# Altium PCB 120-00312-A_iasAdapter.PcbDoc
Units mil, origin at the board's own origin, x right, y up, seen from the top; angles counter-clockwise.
Board outline 1760 x 899 mil, 4 copper layers (Top Layer, L2(GND), L3(V_2V8), Bottom Layer), stack 40.578 mil thick; 12 components, 22 nets, 104 pads, 83 vias.
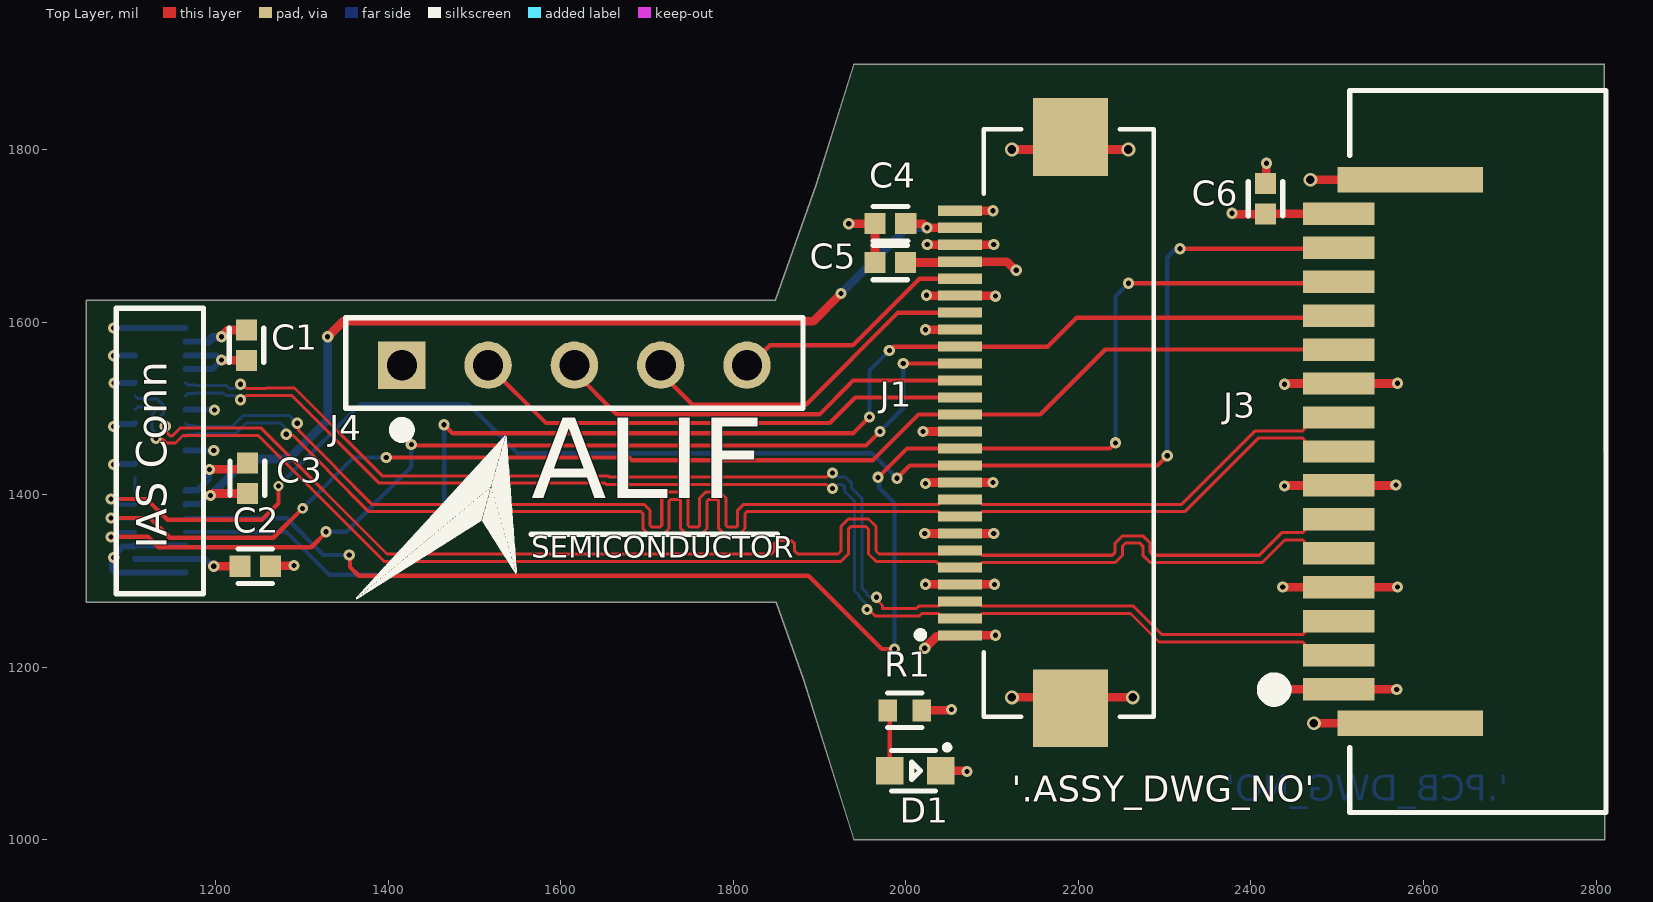
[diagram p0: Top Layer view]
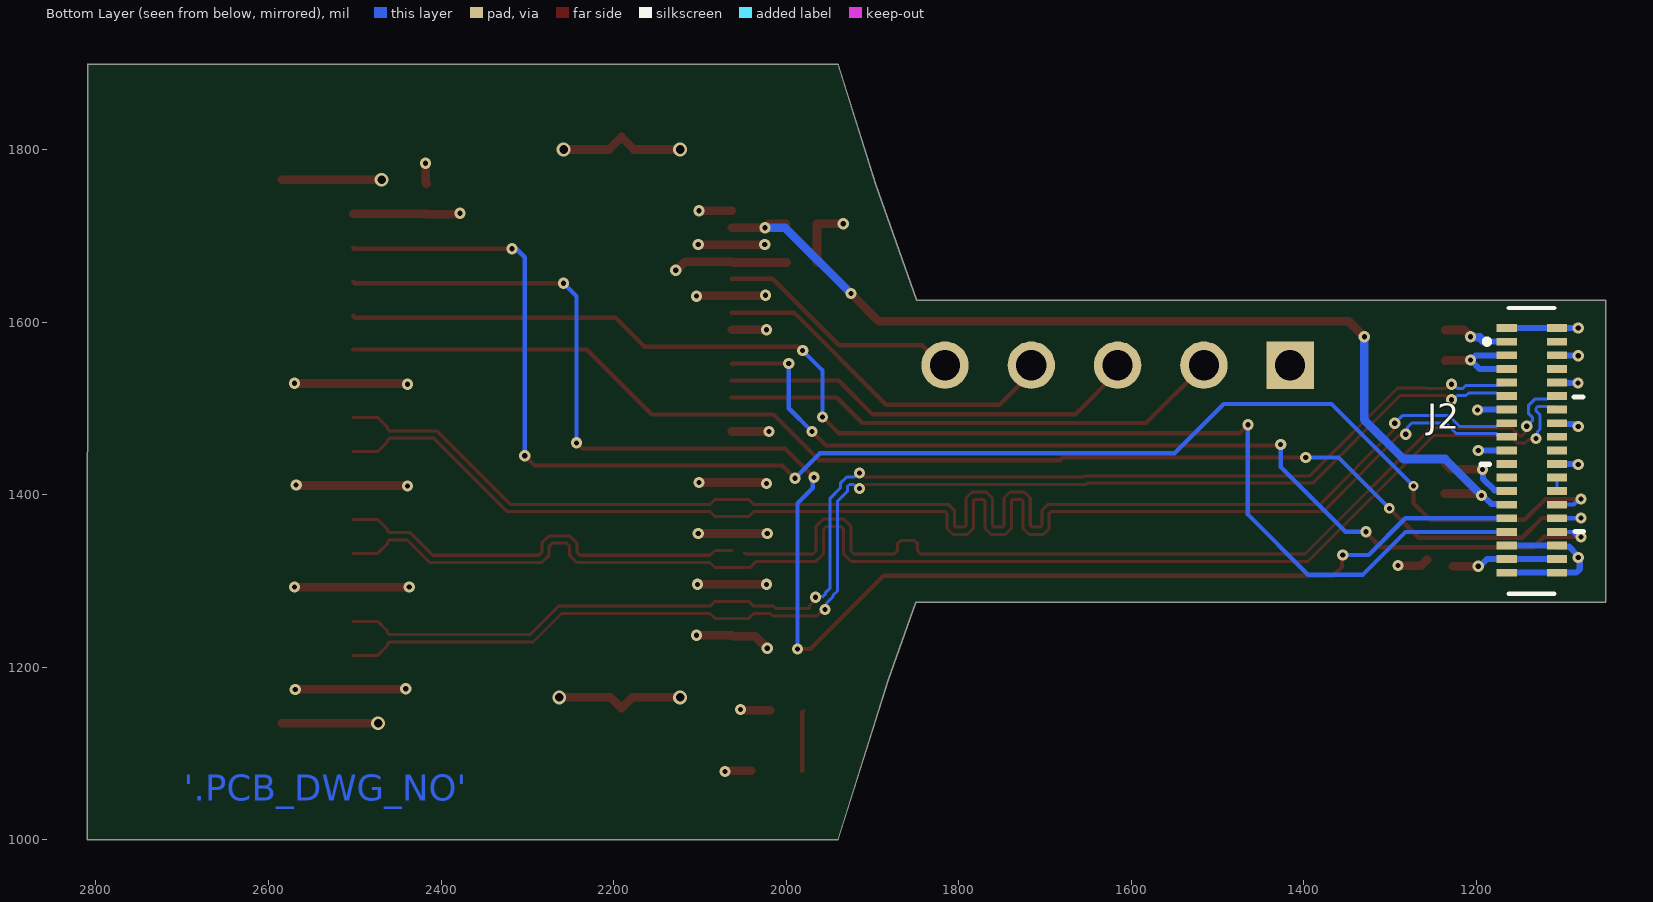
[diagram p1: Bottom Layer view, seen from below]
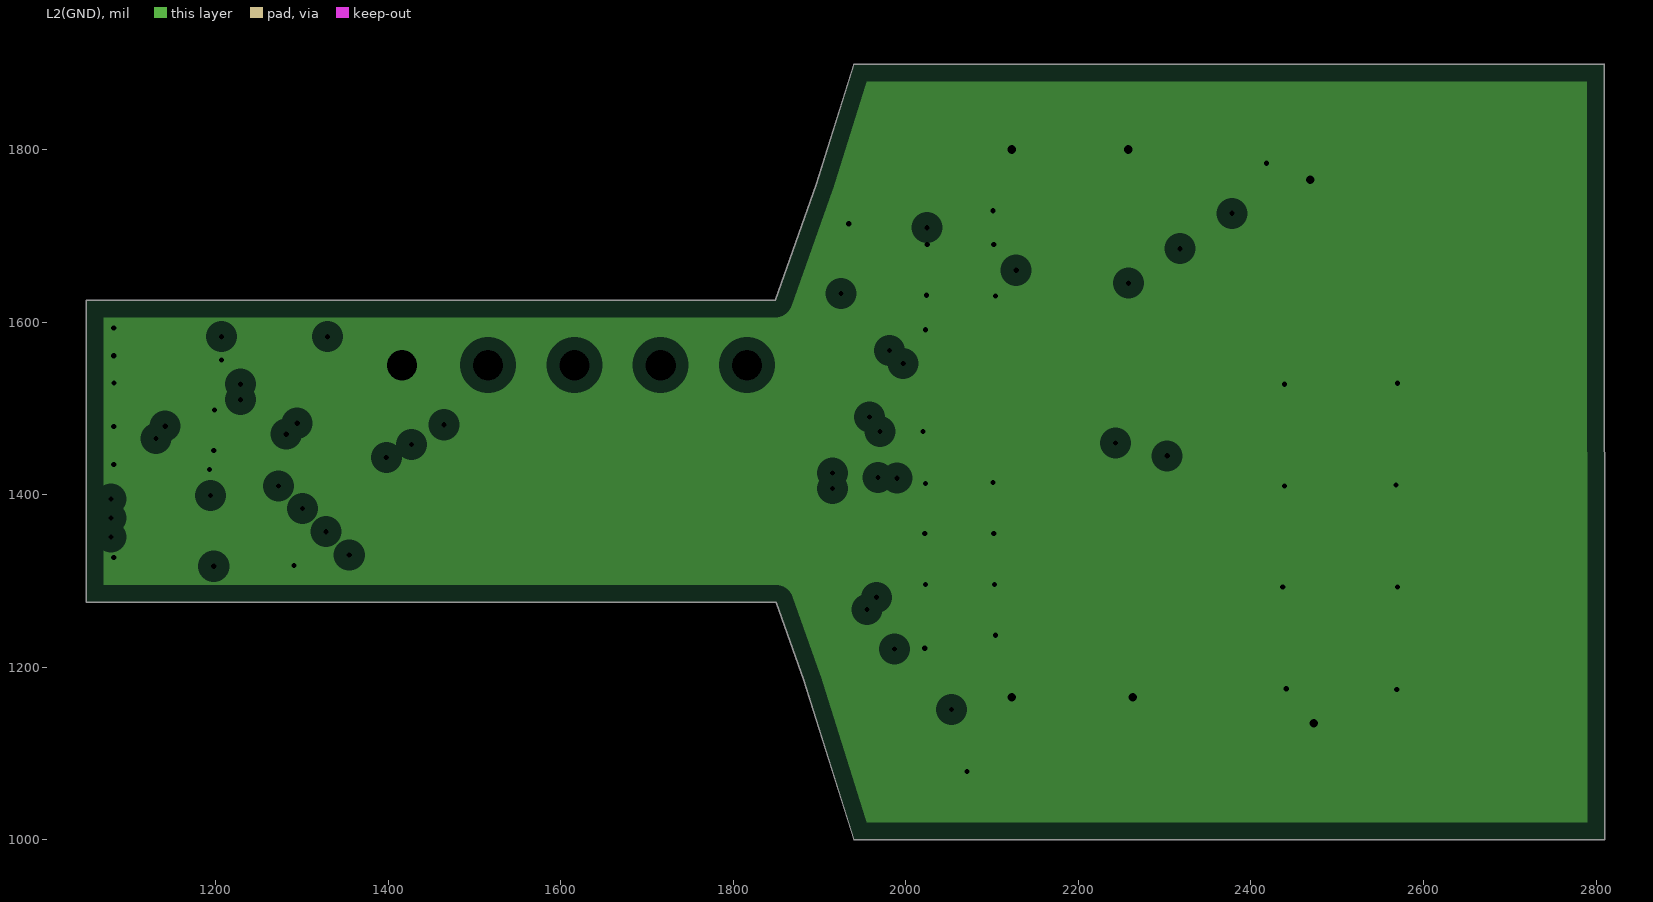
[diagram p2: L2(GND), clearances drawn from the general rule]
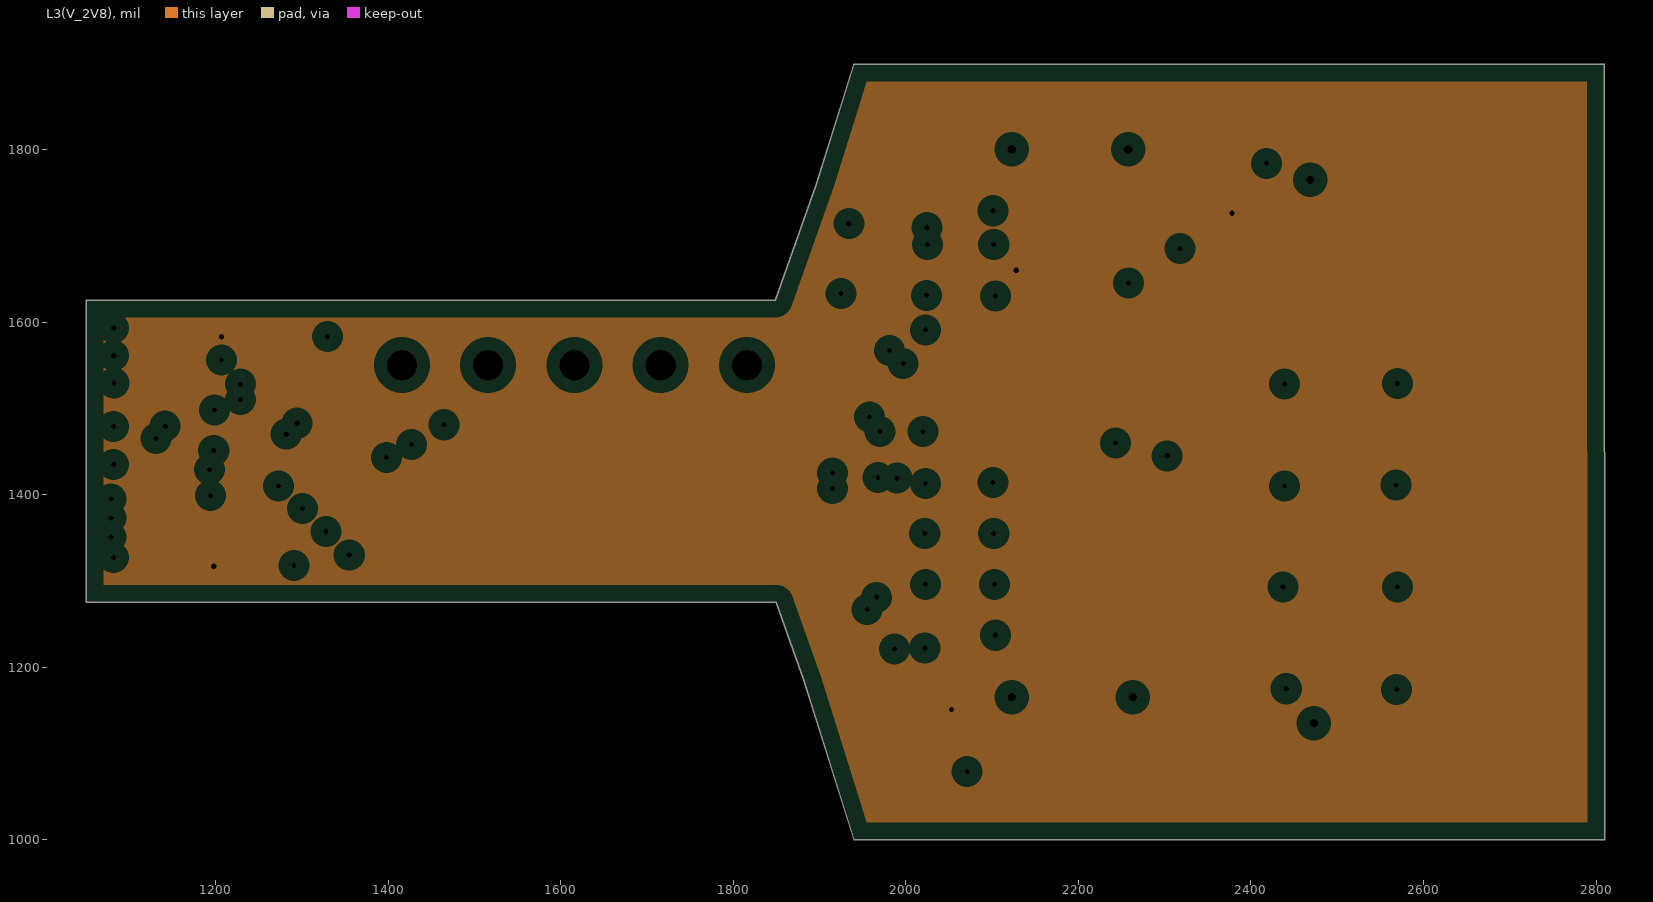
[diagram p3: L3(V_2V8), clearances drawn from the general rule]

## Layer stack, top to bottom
Top Solder: solder mask 0.4, Solder Resist, Dk 3.5
Top Layer: signal copper 1.4
Dielectric 2: prepreg 4.2, PP-006, Dk 4.1
L2(GND): plane copper 0.689, net GND
Dielectric 1: dielectric 28, FR-4, Dk 4.7
L3(V_2V8): plane copper 0.689, net V_2V8
Dielectric 3: prepreg 4.2, PP-006, Dk 4.1
Bottom Layer: signal copper 1.4
Bottom Solder: solder mask 0.4, Solder Resist, Dk 3.5

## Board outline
1940,1000 1882,1185 1850,1275 1050,1275 1050,1625 1849,1625 1896.5,1759.5 1940,1899 2809.4,1899 2809.55,1898.85 2810,1000

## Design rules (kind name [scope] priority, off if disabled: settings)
BoardOutlineClearance [All] p1: gap=10 ignorepadtopadclearanceinfootprint=FALSE except(0: Arc-SplitContinuation Track-SplitContinuation SMDPad-SplitContinuation THPad-SplitContinuation Via-SplitContinuation Fill-SplitContinuation Poly-SplitContinuation Region-SplitContinuation Text-SplitContinuation; 5: Fill-OutlineEdge Poly-OutlineEdge Region-OutlineEdge Text-OutlineEdge; 15: Arc-OutlineEdge Track-OutlineEdge SMDPad-OutlineEdge THPad-OutlineEdge Via-OutlineEdge)
Clearance [All] p1: gap=5 ignorepadtopadclearanceinfootprint=FALSE
DiffPairsRouting [InDifferentialPairClass('All Differential Pairs')] p1: maxlimit=5 minlimit=3 mostfreqgap=5 toplayer_minwidth=3.5 toplayer_maxwidth=4.6 toplayer_prefwidth=4.6 bottomlayer_minwidth=3.5 bottomlayer_maxwidth=4.6 bottomlayer_prefwidth=4.6 maxuncoupledlength=100
MatchedLengths MatchLengths_xSignals_J2_J1 [InxSignalClass('xSignals_J2_J1_MatchLengthsClass')] p1: tolerance=20 checknetsindiffpair=FALSE checkdiffpairvsdiffpair=TRUE checkxsignals=TRUE checkothers=TRUE
MinimumSolderMaskSliver [All] p1: minsoldermaskwidth=0
PlaneClearance [All] p1: clearance=15
PlaneConnect GroundPlane [All] p1: planeconnectstyle=Direct reliefexpansion=20 reliefentries=4 reliefconductorwidth=10 reliefairgap=10
PolygonConnect [InNet('GND')] p1: connectstyle=Direct reliefconductorwidth=10 reliefentries=4 polygonreliefangle="90 Angle" airgapwidth=10
RoutingVias [All] p1: holewidth=28 width=50 viastyle="Through Hole" minholewidth=6 minwidth=12 maxholewidth=10 maxwidth=16
SilkToSilkClearance [All] p1: silktosilkclearance=4
SilkToSolderMaskClearance [IsPad] p1: minsilkscreentomaskgap=4 clearancetoexposedcopper=TRUE
SolderMaskExpansion [All] p1: expansion=4 istentingtop=FALSE
Width [All] p1: maxlimit=10 minlimit=3 preferedwidth=5 minimp=50.000000 maximp=50.000000 favimp=50.000000
24 further rules are at their usual default settings.

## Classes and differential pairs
differential pair class MIPI_CSI_C: MIPI_CSI_C
differential pair class MIPI_CSI_1: MIPI_CSI_1
differential pair class MIPI_CSI_0: MIPI_CSI_0
component class 1-RevisionHistory: ZF1 ZLBL1
differential pair MIPI_CSI_C: +MIPI_CSI_C_P -MIPI_CSI_C_N
differential pair MIPI_CSI_1: +MIPI_CSI_1_P -MIPI_CSI_1_N
differential pair MIPI_CSI_0: +MIPI_CSI_0_P -MIPI_CSI_0_N

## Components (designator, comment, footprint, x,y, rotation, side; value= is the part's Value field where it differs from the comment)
C1 "Cap" CAPC0402-01 1236,1573 r90 top value=100n
C2 "Cap" CAPC0402-01 1246,1317 r180 top value=100n
C3 "Cap" CAPC0402-01 1237,1419 r270 top value=100n
C4 "Cap" CAPC0402-01 1982.28,1714 r0 top value=100n
C5 "Cap" CAPC0402-01 1982,1669 r0 top value=100n
C6 "Cap" CAPC0402-01 2417,1742.72 r270 top value=100n
D1 "D LED2" LED_0603-GRN_AK 2011,1080 r0 top value=GREEN
J1 "5051102696" CONN_FPC_BOT-ENT_FRONT-LOCK_0.50_26 2183,1483.43 r90 top locked
J2 "BM20B(0.8)-34DP-0.4V(51)" CONN_FPC_BM20B(0.8)-34DP-0.4V(51) 1135.87,1451.25 r270 bottom locked
J3 "SFW15R-2STE1LF" CONN_FPC_BOT-ENT_FRONT-LOCK_1.0_15 2663,1450 r90 top locked
J4 "TSW-105-07-G-S" CONN_SAMTEC_CON5_1X5_TU_TSW_dni 1616,1550 r0 top
R1 "Res3" RESC0402-01 1999,1150 r180 top value=1K82

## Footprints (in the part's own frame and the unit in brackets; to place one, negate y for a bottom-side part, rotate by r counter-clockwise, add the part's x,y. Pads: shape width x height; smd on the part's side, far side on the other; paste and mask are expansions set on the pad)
CAPC0402-01 [mm] "Chip Capacitor, Body 1.0x0.5mm, Height 0.6mm, IPC Medium Density"
  rect 0.62x0.62 smd: 1(-0.45,0) 2(0.45,0)
  silkscreen extent -0.51,-0.51 0.51,0.51, body extent -0.55,-0.3 0.55,0.3, height 0.6
CONN_FPC_BM20B(0.8)-34DP-0.4V(51) [mm]
  rect 0.23x0.6 smd paste-1 mask+0.05: 1(-3.2,-0.74) 2(-2.8,-0.74) 3(-2.4,-0.74) 4(-2,-0.74) 5(-1.6,-0.74) 6(-1.2,-0.74) 7(-0.8,-0.74) 8(-0.4,-0.74) 9(0,-0.74) 10(0.4,-0.74) 11(0.8,-0.74) 12(1.2,-0.74) 13(1.6,-0.74) 14(2,-0.74) 15(2.4,-0.74) 16(2.8,-0.74) 17(3.2,-0.74) 18(3.2,0.74) 19(2.8,0.74) 20(2.4,0.74) 21(2,0.74) 22(1.6,0.74) 23(1.2,0.74) 24(0.8,0.74) 25(0.4,0.74) 26(0,0.74) 27(-0.4,0.74) 28(-0.8,0.74) 29(-1.2,0.74) 30(-1.6,0.74) 31(-2,0.74) 32(-2.4,0.74) 33(-2.8,0.74) 34(-3.2,0.74) 35(3.6,-0.74) 36(3.6,0.74) 37(-3.6,-0.74) 38(-3.6,0.74)
  silkscreen extent -4.19,-1.5 4.22,1.52, body extent -4.1,-0.92 4.1,0.86, height 0.66
CONN_FPC_BOT-ENT_FRONT-LOCK_0.50_26 [mm]
  rect 0.3x1.3 smd: 1(-6.262,3.048) 2(-5.762,3.048) 3(-5.262,3.048) 4(-4.762,3.048) 5(-4.262,3.048) 6(-3.762,3.048) 7(-3.262,3.048) 8(-2.762,3.048) 9(-2.262,3.048) 10(-1.762,3.048) 11(-1.262,3.048) 12(-0.762,3.048) 13(-0.262,3.048) 14(0.238,3.048) 15(0.738,3.048) 16(1.238,3.048) 17(1.738,3.048) 18(2.238,3.048) 19(2.738,3.048) 20(3.238,3.048) 21(3.738,3.048) 22(4.238,3.048) 23(4.738,3.048) 24(5.238,3.048) 25(5.738,3.048) 26(6.238,3.048)
  rect 2.286x2.2 smd: MT1(-8.407,-0.202) MT2(8.407,-0.202)
  silkscreen extent -8.66,-2.65 8.64,4.32, body extent -8.68,-2.68 8.62,3.07, height 2
CONN_FPC_BOT-ENT_FRONT-LOCK_1.0_15 [mil] "Raspberry PI 15 pin camera connector"
  rect 26x83 smd paste+0 mask+0: 1(-275.59,161.06) 2(-236.22,161.06) 3(-196.85,161.06) 4(-157.48,161.06) 5(-118.11,161.06) 6(-78.74,161.06) 7(-39.37,161.06) 8(0,161.06) 9(39.37,161.06) 10(78.74,161.06) 11(118.11,161.06) 12(157.48,161.06) 13(196.85,161.06) 14(236.22,161.06) 15(275.59,161.06)
  rect 30x169 smd paste+0 mask+0: MT1(-314.96,78.38) MT2(314.96,78.38)
  silkscreen extent -418,-149 418,246, body extent -409,-66 409,190, height 106
CONN_SAMTEC_CON5_1X5_TU_TSW_dni [mil]
  rect 55x55 / inner round 60 / far side rect 55x55 hole 35 paste-99999 mask+0: 1(-200,0)
  round 55 / inner round 60 / far side round 55 hole 35 paste-99999 mask+0: 2(-100,0) 3(0,0) 4(100,0) 5(200,0)
  silkscreen extent -265,-80 265,55
LED_0603-GRN_AK [mm] "SMT LED 0603 Green"
  rect 0.8x0.8 smd: A(-0.75,0) K(0.75,0)
  silkscreen extent -0.7,-0.6 0.97,0.71, body extent -0.8,-0.4 0.8,0.4, height 0.8
RESC0402-01 [mm] "Chip Resistor, Body 1.0x0.5mm, IPC Medium Density"
  rect 0.55x0.65 smd: 1(-0.5,0) 2(0.5,0)
  silkscreen extent -0.51,-0.51 0.51,0.51, body extent -0.52,-0.27 0.53,0.28, height 0.4

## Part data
C1 C2 C3 C4 C5 C6: library part Cap_SMT, "Cap,100nF,10%,50V,X7R,0402", Manufacturer 1=TDK, Manufacturer 2=Samsung, Manufacturer 3=Walsin, Manufacturer Part Number 1=C1005X7R1H104K050BE, Manufacturer Part Number 2=CL05B104KB54PNC, Manufacturer Part Number 3=0402B104K500CT, Tolerance=10%, Voltage=50V
D1: "Diode,LED,Green 573nm,300mcd @ 20mA,0603", Manufacturer 1=Wurth, Manufacturer Part Number 1=150060VS86000
J1: library part Conn_FFC_BOT_FRONT-LOCK_0.50_26pin, "Conn,FlatFlex,26 pin,0.50mm,bottom-entry,front-lock,SMT", Manufacturer 1=Molex, Manufacturer 2=HiRose, Manufacturer Part Number 2=TF31-26S-0.5SH(800)
J2: library part CONN_HIROSE_BM20_FPC_34PIN_0.4MM_CAM_MODULE, "Conn,FPC,34 pin,0.4mm pitch, 0,8mm height,SMT", Manufacturer 1=HiRose
J3: library part Conn_FFC_BOT_SLIDE-LOCK_1.00_15pin, "Conn,FlatFlex,15 pin,1.00mm,bottom-entry,slide-locking,SMT", Manufacturer 1=Amphenol
J4: library part Hdr_M_1X5_2M54_STRT_UNSHROUD, "DNI,Hdr, 0.025\" SQ Post Header, Through-hole, Vertical, 2.54 mm Pitch, 5-Pin, Male", Manufacturer=Samtec, Temperature Range="-55 to 125 degC"
R1: "Res,1K82,1%,100ppm,0402", Manufacturer 1=Stackpol, Manufacturer 2=Yageo, Manufacturer 3=Bourns, Manufacturer Part Number 1=RMCF0402FT1K82, Manufacturer Part Number 2=RC0402FR-071K82L, Manufacturer Part Number 3=CR0402-FX-1821GLF, Tolerance=1%

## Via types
v1: diameter 13, hole 6, Top Layer to Bottom Layer, 75 vias
v2: diameter 16, hole 10, Top Layer to Bottom Layer, 6 vias
v3: diameter 12, hole 6, Top Layer to Bottom Layer, 2 vias

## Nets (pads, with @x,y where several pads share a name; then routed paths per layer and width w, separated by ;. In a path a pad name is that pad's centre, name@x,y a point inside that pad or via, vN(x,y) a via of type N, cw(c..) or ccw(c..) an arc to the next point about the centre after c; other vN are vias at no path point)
CXT_SEL: J1.22 J4.5 | length 288.5
  Top Layer w5: J4.5 1819.5,1550 1842.5,1573 1938.73,1573 2016.01,1650.28 J1.22
FLASH: J1.18 J2.15 J3.12 | length 1582.9
  Top Layer w5: v1(1465,1481) 1475,1471 1939,1471 v1(1958,1490) ; v1(1981,1567) 1985.54,1571.54 J1.18 2164.54,1571.54 2198,1605 2499.46,1605 J3.12
  Bottom Layer w5: J2.15 1282.24,1356.76 1332,1307 1395,1307 1465,1377 v1(1465,1481) ; v1(1958,1490) 1958,1544 v1(1981,1567)
GND: C1.1 C2.1 C3.1 C4.1 C5.1 C6.1 D1.K J1.1 J1.4 J1.7 J1.10 J1.13 J1.19 J1.21 J1.24 J1.26 J1.MT1 J1.MT2 J2.2 J2.3 J2.6 J2.9 J2.12 J2.16 J2.19 J2.25 J2.28 J2.31 J2.33 J2.35 J2.36 J2.37 J2.38 J3.1 J3.4 J3.7 J3.10 J3.MT1 J3.MT2 J4.1 | length 2476.2
  Top Layer w10: v1(1193,1429) 1193.57,1429.57 1229.86,1429.57 C3.1 ; v1(1207,1556) 1207.36,1555.64 1235.64,1555.64 C1.1 ; C2.1@1257.32,1324.57 1264.4,1317.5 1290.5,1317.5 v1(1291,1318) ; v1(1934,1714) C4.1 1964.43,1713.86 1964.43,1669.14 C5.1 ; v1@2019,1473 2019.11,1473.11 J1.13 ; v1(2022,1355) J1.7 v1(2102,1355) ; v1@2022.57,1222.57 2035.98,1235.98 2062.09,1235.98 J1.1 2103.89,1236.89 v1(2104,1237) ; v1(2023,1413) 2024,1413 2025.06,1414.06 J1.10 2100.94,1414.06 v1(2101,1414) ; v1(2023,1591) 2025,1591 2025.22,1591.22 J1.19 ; v1(2023,1296) J1.4@2062.97,1295.97 ; v1(2024,1631) 2024.41,1630.59 J1.21 2063.3,1630.3 2103.7,1630.3 v1(2104,1630) ; v1(2025,1690) 2025.35,1689.65 J1.24 2101.65,1689.65 v1(2102,1690) ; D1.K 2069.46,1080 2070.46,1079 v1(2071,1079) ; J1.26 v1(2101,1729) ; J1.4@2063.03,1295.97 v1(2103,1296) ; v2(2123,1165) 2178.38,1165 J1.MT1 2203.53,1165 v2(2263,1165) ; v2(2123,1800) 2176.53,1800 J1.MT2 2205.38,1800 v2(2258,1800) ; C6.1 2417.62,1761.05 2417.62,1783.62 v1(2418,1784) ; v1(2437,1293) 2437.48,1292.52 J3.4 2569.52,1292.52 v1(2570,1293) ; v1(2439,1410) 2439.63,1410.63 J3.7 2567.63,1410.63 v1(2568,1411) ; v1(2439,1528) 2439.74,1528.74 J3.10 2569.74,1528.74 v1(2570,1529) ; v1(2441,1175) 2441.59,1174.41 J3.1 2568.59,1174.41 v1(2569,1174) ; v2@2471,1765 v2(2469,1765) v2(2469,1765) J3.MT2 ; v2(2473,1135) v2(2473,1135) J3.MT1
  Bottom Layer w7: v1(1082,1435) 1082.25,1435.25 1105.98,1435.25 J2.25@1106.48,1435.75 ; v1(1082,1479) 1083.62,1479 1086.34,1481.72 1105.45,1481.72 J2.28@1106.61,1482.87 ; v1(1082,1561) 1082.24,1561.24 J2.33@1106.49,1561.24 ; v1(1082,1593) J2.38 ; v1(1082.25,1529.25) 1082.62,1529.62 1106.35,1529.62 J2.31 ; J2.38 J2.37 ; J2.35 J2.36 1084.48,1309.52 1080.38,1313.62 1080.38,1324.03 1083.15,1326.8 1083.15,1330.04 1093.09,1339.99 1105.7,1339.99 J2.19 J2.16 ; J2.12 1166.03,1405.04 1179.04,1405.04 1192.62,1418.62 1192.62,1428.62 v1(1193,1429) ; J2.9 v1@1197.75,1451.25 ; J2.6 v1@1198.5,1498.5 ; J2.3 1196.74,1545.74 v1(1207,1556) ; J2.2 1200.97,1561.49 v1@1206.46,1556 ; v1(1291,1318) v1@1291,1319.62
  Bottom Layer w10: v1@1197.75,1451.25 v1(1198,1451) ; v1@1198.5,1498.5 v1(1199,1498) ; v1@1206.46,1556 v1(1207,1556)
  other v1: 2022,1222 1082,1327 2020,1473
I2C_ADDR: J2.34
I2C_SCL: J1.12 J2.14 J3.13 | length 1826.7
  Top Layer w5: v1(1355,1330) 1356,1329 1356,1316 1366,1306 1887.14,1306 1972.14,1221 v1(1987,1221) ; v1(1968,1420) 2001.43,1453.43 J1.12 2236.43,1453.43 v1(2243,1460) ; v1(2258,1645) 2500.09,1645 J3.13
  Bottom Layer w5: J2.14 1282.49,1372.51 1325,1330 v1(1355,1330) ; v1(1968,1420) 1969.34,1418.66 1969.34,1407.66 1987,1390 v1(1987,1221) ; v1(2243,1460) 2243,1630 v1(2258,1645)
I2C_SDA: J1.11 J2.22 J3.14 | length 1811.7
  Top Layer w5: v1(1079,1395) 1120,1395 1144,1371 1254,1371 1273,1390 v3(1273,1410) ; v1(1990,1419) 2004.74,1433.74 J1.11 2291.74,1433.74 v1(2303,1445) ; v1(2318,1685) 2500.72,1685 J3.14
  Bottom Layer w5: v1(1079,1395) 1081.05,1395 1087.42,1388.63 1106.36,1388.63 J2.22 ; v3(1273,1410) 1368,1505 1493,1505 1550,1448 1961,1448 v1(1990,1419) ; v1(2303,1445) 2303,1675 2313,1685 v1(2318,1685)
INT: J1.20 J4.4 | length 415.6
  Top Layer w5: J4.4 1716,1541.07 1753.07,1504 1884,1504 1990.91,1610.91 J1.20
MCLK: J2.32
METER: J1.15 J4.2 | length 587
  Top Layer w5: J4.2 1583,1483 1912,1483 1941.48,1512.48 J1.15
MIPI_CSI_0_N: J1.2 J2.5 J3.2 | length 1548.9
  Top Layer w3.5: v1(1229,1510) 1231.05,1510 1235.8,1514.75 1262.15,1514.75 1262.4,1515 1288,1515 1389.75,1413.25 1651.37,1413.25 1652.87,1411.75 1908.2,1411.75 1912.95,1407 v1(1915,1407) ; v1(1954.93,1266.81) 1957.01,1266.81 1964.28,1259.54 2015.93,1259.54 2018.56,1262.17 2037.72,1262.17 2043.31,1256.57 J1.2 2082.69,1256.57 2088.28,1262.17 2260.46,1262.17 2293.41,1229.21 2460.14,1229.21 2462.19,1227.16 2462.19,1225.03 2473.44,1213.78 J3.2
  Bottom Layer w3.5: J2.5 1167.78,1517.02 1176.26,1517.02 1177.11,1517.87 1209.06,1517.87 1212.18,1514.75 1222.2,1514.75 1226.95,1510 v1(1229,1510) ; v1(1915,1407) 1917.05,1407 1921.8,1411.75 1926.75,1411.75 1928.8,1409.7 1928.8,1404.18 1940.64,1392.34 1940.64,1288.33 1945.75,1283.22 1945.75,1281.71 1953.11,1274.35 1953.11,1268.62 v1(1954.93,1266.81)
MIPI_CSI_0_P: J1.3 J2.4 J3.3 | length 1549.1
  Top Layer w3.5: v1(1229,1528) 1231.05,1528 1235.8,1523.25 1258.63,1523.25 1258.88,1523.5 1291.52,1523.5 1393.27,1421.75 1654.89,1421.75 1656.39,1420.25 1908.2,1420.25 1912.95,1425 v1(1915,1425) ; v1(1966,1281) 1966,1278.43 1972.95,1271.48 1972.95,1268.04 2012.41,1268.04 2015.04,1270.67 2037.72,1270.67 2043.31,1276.26 J1.3 2082.69,1276.26 2088.28,1270.67 2263.98,1270.67 2296.93,1237.71 2460.14,1237.71 2462.19,1239.76 2462.19,1241.9 2473.44,1253.15 J3.3
  Bottom Layer w3.5: J2.4 1167.78,1527.21 1176.26,1527.21 1177.11,1526.37 1212.58,1526.37 1215.7,1523.25 1222.2,1523.25 1226.95,1528 v1(1229,1528) ; v1(1915,1425) 1917.05,1425 1921.8,1420.25 1930.27,1420.25 1937.3,1413.22 1937.3,1407.7 1949.14,1395.86 1949.14,1291.85 1954.25,1286.74 1954.25,1285.23 1957.43,1282.05 1964.95,1282.05 v1(1966,1281)
MIPI_CSI_1_N: J1.5 J2.29 J3.5 | length 1624.7
  Top Layer w3.5: v1(1130.91,1464.87) 1131.91,1463.87 1139.53,1463.87 1143.7,1459.7 1153.64,1459.7 1162.44,1468.5 1249.5,1468.5 1395.34,1322.66 1917.13,1322.66 1924.89,1322.66 1933.4,1331.16 1933.4,1359.72 1936.92,1363.24 1953.37,1363.24 1956.9,1359.72 1956.9,1331.16 1965.4,1322.66 1985,1322.66 2034.65,1322.66 2041.68,1315.63 J1.5 2082.69,1315.63 2088.28,1321.22 2235,1321.22 2242.76,1321.22 2251.26,1329.73 2251.26,1340.28 2254.79,1343.81 2271.24,1343.81 2274.76,1340.28 2274.76,1329.73 2283.27,1321.22 2298,1321.22 2413.24,1321.22 2439.35,1347.32 2460.14,1347.32 2462.19,1345.27 2462.19,1343.14 2473.44,1331.89 J3.5
  Bottom Layer w3.5: J2.29 1109.51,1501.27 1118,1501.27 1118.84,1502.12 1128.99,1502.12 1131.04,1500.07 1131.04,1497.17 1126.38,1492.51 1126.38,1475.86 1129.1,1473.14 1129.1,1466.69 v1(1130.91,1464.87)
MIPI_CSI_1_P: J1.6 J2.30 J3.6 | length 1627.2
  Top Layer w3.5: v1(1141.69,1479.29) 1143.51,1477.47 1143.51,1471.91 1147.22,1468.2 1150.12,1468.2 1158.92,1477 1253.02,1477 1398.86,1331.16 1837,1331.16 1844.2,1331.16 1847.72,1334.68 1847.72,1343.12 1851.25,1346.64 1867.7,1346.64 1871.22,1343.12 1871.22,1334.68 1874.75,1331.16 1900,1331.16 1917.13,1331.16 1921.37,1331.16 1924.9,1334.68 1924.9,1363.24 1933.4,1371.74 1956.89,1371.74 1965.4,1363.24 1965.4,1334.68 1968.92,1331.16 1985,1331.16 2047.34,1331.16 J1.6@2048.72,1332.54 ; J1.6 2082.69,1335.32 2088.28,1329.72 2235,1329.72 2239.24,1329.72 2242.76,1333.25 2242.76,1343.8 2251.27,1352.31 2274.76,1352.31 2283.26,1343.8 2283.26,1333.25 2286.79,1329.72 2298,1329.72 2409.72,1329.72 2435.82,1355.82 2460.14,1355.82 2462.19,1357.88 2462.19,1360.01 2473.44,1371.26 J3.6
  Bottom Layer w3.5: J2.30 1109.51,1511.47 1118,1511.47 1118.84,1510.62 1132.51,1510.62 1139.54,1503.59 1139.54,1493.65 1134.88,1488.99 1134.88,1486.09 v1(1141.69,1479.29) v1@1141.1,1479.87
MIPI_CSI_C_N: J1.8 J2.8 J3.8 | length 1622.2
  Top Layer w3.5: v1(1282,1470) 1283.45,1468.55 1290.17,1468.55 1330.48,1428.24 1330.48,1427.53 1377.73,1380.28 1688,1380.28 1691.52,1380.28 1693.16,1380.28 1695.21,1378.23 1695.21,1360.71 1702.21,1353.71 1718.71,1353.71 1725.71,1360.71 1725.71,1392.49 1727.73,1394.51 1737.18,1394.51 1739.21,1392.49 1739.21,1360.71 1746.21,1353.71 1762.71,1353.71 1769.71,1360.71 1769.71,1392.49 1771.73,1394.51 1781.18,1394.51 1783.21,1392.49 1783.21,1360.71 1790.21,1353.71 1806.71,1353.71 1813.71,1360.71 1813.71,1378.23 1815.76,1380.28 1820,1380.28 2037.72,1380.28 2043.31,1374.69 J1.8 2082.69,1374.69 2088.28,1380.28 2323.3,1380.28 2408.46,1465.43 2460.14,1465.43 2462.19,1463.38 2462.19,1461.25 2473.44,1450 J3.8
  Bottom Layer w3.5: J2.8 1167.78,1469.78 1176.26,1469.78 1177.11,1470.62 1223.14,1470.62 1235.47,1482.96 1275.05,1482.96 1280.18,1477.83 1280.18,1471.82 v1(1282,1470)
MIPI_CSI_C_P: J1.9 J2.7 J3.9 | length 1622.6
  Top Layer w3.5: v1(1294.73,1482.73) 1296.18,1481.28 1296.18,1474.56 1338.98,1431.76 1338.98,1431.05 1381.25,1388.78 1688,1388.78 1696.68,1388.78 1703.71,1381.75 1703.71,1364.23 1705.73,1362.21 1715.18,1362.21 1717.21,1364.23 1717.21,1396.01 1724.21,1403.01 1740.71,1403.01 1747.71,1396.01 1747.71,1364.23 1749.73,1362.21 1759.18,1362.21 1761.21,1364.23 1761.21,1396.01 1768.21,1403.01 1784.71,1403.01 1791.71,1396.01 1791.71,1364.23 1793.73,1362.21 1803.18,1362.21 1805.21,1364.23 1805.21,1381.75 1812.24,1388.78 1820,1388.78 2037.72,1388.78 2043.31,1394.37 J1.9 2082.69,1394.37 2088.28,1388.78 2319.78,1388.78 2404.93,1473.93 2460.14,1473.93 2462.19,1475.99 2462.19,1478.12 2473.44,1489.37 J3.9
  Bottom Layer w3.5: J2.7 1167.78,1479.97 1176.26,1479.97 1177.11,1479.12 1219.62,1479.12 1231.95,1491.46 1286,1491.46 v1(1294.73,1482.73)
NetD1_A: D1.A R1.2 | length 70.9
  Top Layer w3.5: R1.2 R1.2@1981.47,1147.84
  Top Layer w5: D1.A R1.2@1981.47,1147.84
RESETn: J1.14 J2.21 J3.11 | length 1553.2
  Top Layer w5: v1(1079,1373) 1124,1373 1147,1350 1267,1350 v3(1301,1384) ; v1(1398,1443) 1679.58,1443 1682.58,1440 1962,1440 2014.8,1492.8 J1.14 2155.8,1492.8 2231.11,1568.11 J3.11
  Bottom Layer w5: v1(1079,1373) 1079.24,1372.76 1106.49,1372.76 J2.21 ; v3(1301,1384) 1360,1443 v1(1398,1443)
TRIGGER: J1.17 J2.20 | length 1155.7
  Top Layer w5: v1(1079,1351) 1122,1351 1133.95,1339.05 1311.05,1339.05 1328,1356 v1(1328,1357) ; v1(1427,1458) 1428,1457 1954,1457 v1(1970,1473) ; v1(1997,1552) 1997.15,1551.85 J1.17 J1.17@2062.07,1550.93
  Bottom Layer w5: v1(1079,1351) 1080.53,1352.53 1084.54,1352.53 1088.77,1356.76 J2.20 ; v1(1328,1357) 1352,1357 1427,1432 v1(1427,1458) ; v1(1970,1473) 1997,1500 v1(1997,1552)
V_1V2: J2.23 J2.24 | length 15.7
  Bottom Layer w3: J2.23 J2.24
V_1V8: C3.2 C4.2 J1.25 J2.13 | length 1158
  Top Layer w10: v1(1194.11,1398.89) 1194.92,1398.89 1197.31,1401.28 C3.2 ; v1(1330,1583) 1348,1601 1893,1601 v1(1925,1633) ; C4.2 2020,1714 v1(2024.67,1709.33) J1.25
  Bottom Layer w7: J2.13 1166.03,1389.29 1182.88,1389.29 1192.48,1398.89 v1(1194.11,1398.89)
  Bottom Layer w10: v1(1194.11,1398.89) 1236.51,1441.3 1284.7,1441.3 1330,1486.59 v1(1330,1583) ; v1(1925,1633) 2001.33,1709.33 v1(2024.67,1709.33)
V_2V8: C1.2 C2.2 C5.2 C6.2 J1.23 J2.1 J2.17 J2.18 J3.15 R1.1 | length 493
  Top Layer w10: v1(1198,1317) C2.2@1227.28,1317 ; v1(1207,1583) 1207,1583.47 1214.24,1590.72 C1.2 ; C5.2 2042.35,1669 2042.41,1669.06 2062.09,1669.06 J1.23 2117.23,1669.96 2127.19,1660 v1(2128,1660) ; R1.1 2051.19,1150 2052.19,1151 v1(2053,1151) ; v1(2378,1726) 2378.81,1726 2379.81,1725 C6.2 2417.3,1725.3 2501.64,1725.3 J3.15
  Bottom Layer w7: J2.18 1188.11,1325.27 1196.38,1317 v1(1198,1317) ; J2.1 1191.24,1577.24
  Bottom Layer w10: 1191.24,1577.24 1196.43,1582.43 1206.43,1582.43 v1(1207,1583)
XSLEEP: J1.16 J4.3 | length 491.7
  Top Layer w5: J4.3 1616,1542 1665,1493 1900,1493 1936,1529 1936,1529.24 1938.93,1532.17 J1.16
pads on no net: J2.10 J2.11 J2.26 J2.27

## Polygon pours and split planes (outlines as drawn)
GND on L2(GND) (split plane): 2789.89,1020.1 1954.76,1020.1 1901.18,1191.01 1901.03,1191.36 1900.94,1191.73 1868.94,1281.73 1868.72,1282.2 1868.57,1282.69 1867.88,1283.98 1867.26,1285.3 1866.95,1285.71 1866.71,1286.17 1865.78,1287.29 1864.92,1288.47 1864.54,1288.81 1864.21,1289.21 1863.08,1290.14 1862,1291.12 1861.56,1291.38 1861.17,1291.71 1859.88,1292.4 1858.63,1293.15 1858.14,1293.32 1857.69,1293.57 1856.3,1293.99 1854.92,1294.48 1854.41,1294.56 1853.92,1294.71 1852.47,1294.85 1851.03,1295.07 1850.51,1295.05 1850,1295.1 1070.1,1295.1 1070.1,1604.9 1849,1604.9 1849.53,1604.96 1850.07,1604.93 1851.49,1605.15 1852.92,1605.29 1853.43,1605.44 1853.96,1605.53 1855.32,1606.02 1856.69,1606.43 1857.16,1606.69 1857.67,1606.87 1858.9,1607.61 1860.17,1608.29 1860.58,1608.63 1861.04,1608.91 1862.1,1609.88 1863.21,1610.79 1863.55,1611.2 1863.95,1611.57 1864.8,1612.72 1865.71,1613.83 1865.96,1614.31 1866.28,1614.74 1866.89,1616.04 1867.57,1617.31 1867.72,1617.82 1867.95,1618.31 1915.45,1752.81 1915.54,1753.17 1915.69,1753.52 1954.78,1878.9 2789.46,1878.9
V_2V8 on L3(V_2V8) (split plane): 2789.89,1020.1 1954.76,1020.1 1901.18,1191.01 1901.03,1191.36 1900.94,1191.73 1868.94,1281.73 1868.72,1282.2 1868.57,1282.69 1867.88,1283.98 1867.26,1285.3 1866.95,1285.71 1866.71,1286.17 1865.78,1287.29 1864.92,1288.47 1864.54,1288.81 1864.21,1289.21 1863.08,1290.14 1862,1291.12 1861.56,1291.38 1861.17,1291.71 1859.88,1292.4 1858.63,1293.15 1858.14,1293.32 1857.69,1293.57 1856.3,1293.99 1854.92,1294.48 1854.41,1294.56 1853.92,1294.71 1852.47,1294.85 1851.03,1295.07 1850.51,1295.05 1850,1295.1 1070.1,1295.1 1070.1,1604.9 1849,1604.9 1849.53,1604.96 1850.07,1604.93 1851.49,1605.15 1852.92,1605.29 1853.43,1605.44 1853.96,1605.53 1855.32,1606.02 1856.69,1606.43 1857.16,1606.69 1857.67,1606.87 1858.9,1607.61 1860.17,1608.29 1860.58,1608.63 1861.04,1608.91 1862.1,1609.88 1863.21,1610.79 1863.55,1611.2 1863.95,1611.57 1864.8,1612.72 1865.71,1613.83 1865.96,1614.31 1866.28,1614.74 1866.89,1616.04 1867.57,1617.31 1867.72,1617.82 1867.95,1618.31 1915.45,1752.81 1915.54,1753.17 1915.69,1753.52 1954.78,1878.9 2789.46,1878.9

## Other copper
Bottom Layer:
  text "'.PCB_DWG_NO'" at 2698,1045 h30

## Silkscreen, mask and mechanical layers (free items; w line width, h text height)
Top Overlay:
  drawing of 12 lines, arcs and shapes, not listed
  text "ALIF" at 1566,1365 h160
  text "IAS Conn" at 1155,1337 h60 r90
  text "SEMICONDUCTOR" at 1566,1318 h43
  text "'.ASSY_DWG_NO'" at 2123,1044 h30
Bottom Solder:
  text "'.PCB_DWG_NO'" at 2698,1045 h30

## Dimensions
1050,1636 to 1940,1953 on Drill Drawing
1140,1591 to 1940,1913 on Drill Drawing
1038,1275 to 1037.5,1450 on Drill Drawing
1024,1450 to 1037,1625 on Drill Drawing
1040,1449 to 1976,1899 on Drill Drawing
1050,1644 to 2810,1911 on Drill Drawing
2828,1000 to 2823,1900 on Drill Drawing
